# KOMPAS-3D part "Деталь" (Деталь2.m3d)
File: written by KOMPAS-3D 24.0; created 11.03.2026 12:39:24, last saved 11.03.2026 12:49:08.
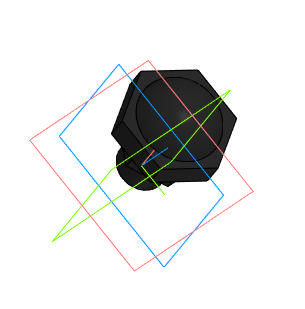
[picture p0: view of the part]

Document properties: Автор: R2D2; Полное имя файла: E:\Работа\Зайцев\БКВ APL-210N Блок концевых выключателей DN.ru\исходные материалы\Деталь2.m3d

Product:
- Part/product: Деталь
    Масса: 0.143875

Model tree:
1. Эскиз:1
2. Элемент вращения:1
     Угол 1 = 360
3. Эскиз:2  (with: Грань.Элемент вращения:1)
4. Элемент выдавливания:1
     Расстояние 2 = 10
5. Эскиз:3  (with: Грань.Элемент вращения:1)
6. Элемент выдавливания:2  (with: Грань.Элемент вращения:1)
     Расстояние 2 = 8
